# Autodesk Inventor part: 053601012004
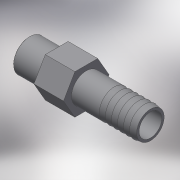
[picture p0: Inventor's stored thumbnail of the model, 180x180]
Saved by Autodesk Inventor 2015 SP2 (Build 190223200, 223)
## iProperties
Created: 2017-10
Part Number: 053601012004
Material: Generic
Description: PLASSON THREADED HOSE NOZZLE 1/4"-12
Document SubType Name: Modeling
Designer: KIM
Density: 1 g/cm^3
Appearance: Default
Author: KIM
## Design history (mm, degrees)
derived "053601.ipt"
feature "Solid1::053601.ipt"
tag "TaggingFeature1"
body "Solid1"
other parameters: "d0" = 49, "d1" = 170 deg, "d2" = 12, "d6" = 9.2099, "d8" = 14.7, "d9" = 13.157, "d10" = 16, "d11" = 11, "d12" = 12, "d13" = 12, "d14" = 0, "d15" = 0.12, "d_" = 12, "E_" = 12, "H_" = 49, "R_" = 13.157, "C_" = 16, "B_" = 12, "Lt_" = 11
